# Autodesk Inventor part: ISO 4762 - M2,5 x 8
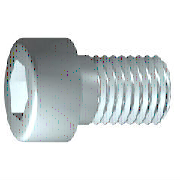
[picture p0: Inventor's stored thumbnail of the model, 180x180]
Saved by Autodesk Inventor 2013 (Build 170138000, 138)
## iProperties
IsCustomPart: 0
Created: 2012-02
Part Number: ISO 4762 - M2,5 x 8
Material: Edelstahl, 440C
Description: Innensechskantschraube
Document SubType Name: Modeling
Standard: ISO 4762
Designer: rYan
Standard Revision: 1998
Standards Organization: DIN
Language: de-DE
Size Designation: M2,5 x 8
Categories: <MemberInstance><Categories><Category DisplayName="Verbindungselemente" InternalName="e4da775c-781d-43d5-af7c-5136215cf5a6" Mnemonic="FSTN"><Category DisplayNam
Density: 7.75 g/cm^3
Mass: 0.572491 g
Surface Area: 1.353 cm^2
Volume: 0.0738699 cm^3
Author: rYan
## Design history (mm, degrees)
sketch "Skizze1"
  geometry: L1 (-0.733, 0)-(8, 0); L2 (8, 0)-(8, 1.25); L3 (8, 1.25)-(1.125, 1.25); L4 (1.125, 1.25)-(0.849, 1.25); L5 (0.849, 1.25)-(0, 1.25); L6 (0, 1.25)-(0, 2.25); L7 (0, 2.25)-(-2.5, 2.25); L8 (-2.5, 2.25)-(-2.5, 1.155); L9 (-2.5, 1.155)-(-1.4, 1.155); L10 (-1.4, 1.155)-(-0.733, 0); L11 (-4.6, 0)-(10.1, 0) reference; L12 (0, -0.45)-(0, 2.7) reference; L13 (1.125, 1.25)-(0, 1.25)
  constraints: 22 end point, 6 parallel, 2 collinear, 2 perpendicular, 1 horizontal, 1 point on line
  dimensions: "d1" = 6.875 distance from line of L3.end L2 (= GEL); "d2" = 0.27615 distance of L4.end L3.end (computed from GAL); "d3" = 2.5 distance between parallel lines of L8 L6 (= KOH); "d4" = 1.1 distance of L8.end L9.end (= INTI); "d5" = 60 deg angle of L10 L1; "d6" = 2.5 diameter of L3 L1 (= GD); "d7" = 2.5 diameter of L5 L1 (= BDM); "d8" = 2.3094 diameter of L9 L1 (= 1.1547 x SW); "d9" = 4.5 diameter of L7 L1 (= KOD); "d26" = 8 distance between parallel lines of L12 L2 (= NLG)
revolve "Körper" sketch "Skizze1" stored, may be unused: angle "d10" = 90 deg
sketch "Skizze2"
  geometry: L1 (0, -3.15)-(0, 3.15) reference; L2 (-3.15, 0)-(3.15, 0) reference; L3 (1.155, 0)-(0.577, -1); L4 (0.577, -1)-(-0.577, -1); L5 (-0.577, -1)-(-1.155, 0); L6 (-1.155, 0)-(-0.577, 1); L7 (-0.577, 1)-(0.577, 1); L8 (0.577, 1)-(1.155, 0); 2 further points
  constraints: 12 end point, 1 coincident, 1 horizontal alignment, 1 point on line, 12 other
extrude "Loch" join sketch "Skizze2" stored distance "d11" = 10; taper "d12" = 0 deg
workplane "Work Plane1"
fillet "Fillet2" dims "d30" = 0.1 (= R)
body "Solid1"
fillet "Rundung1" dims "d17" = 0.25 (= RR)
feature "Gewinde" dims "d13" = 6.875 (= GEL), "d14" = 0
chamfer "Fase1" distance "d15" = 0.27605 (= -0.5 x SPD + 0.5 x GD); stored, may be unused: second distance "d16" = 0.27605 (= GUL), angle "d27" = 45 deg
other parameters: "GD" = 2.5 [user parameter; used in 2 equation terms], "NLG" = 8 [user parameter; used in 1 equation term], "GEL" = 6.875 [user parameter; used in 2 equation terms], "KOD" = 4.5 [user parameter; used in 1 equation term], "KOH" = 2.5 [user parameter; used in 1 equation term], "INTI" = 1.1 [user parameter; used in 1 equation term], "GAL" = 0.27605 (= 0.61345 x PTC) [user parameter; used in 1 equation term], "GUL" = 0.27605 (= 0.61345 x PTC) [user parameter; used in 1 equation term], "BDM" = 2.5 (= NND) [user parameter; used in 1 equation term], "SW" = 2 [user parameter; used in 2 equation terms], "RR" = 0.25 [user parameter; used in 1 equation term], "SPD" = 1.94789 (= NND - 1.2269 x PTC) [user parameter; used in 1 equation term], "d19" = 0, "d28" = 0, "d29" = 0, "R" = 0.1 [user parameter; used in 1 equation term], "TOA" = 30 deg [user parameter], "GD1" = 1.94789 (= THREADDIA - 1.2269 x PTC) [user parameter], "THREADDIA" = 2.5 [user parameter; used in 1 equation term], "FAWI" = 45 deg [user parameter], "TPU" = 22.22222 (computed from PTC) [user parameter], "PTC" = 0.45 [user parameter; used in 5 equation terms], "NND" = 2.5 [user parameter; used in 2 equation terms], "E0" = 2.31 (= 1.155 x SW) [user parameter]
